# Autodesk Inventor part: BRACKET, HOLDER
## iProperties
Title: BRACKET, HOLDER
Author: J. DESIGNER
Revision Number: A
Created: 2000-11
Part Number: ex10-1
Project: ACME
User Status: ECO 20001
Description: HOLDER, BRACKET
Document SubType Name: Modeling
Designer: E. MOSS
Control State: 0
Master: False
Checked Out: False
PropertySet Name: Design Tracking Control
Shininess: 50.0
PropertySet Name: _Private Model Information
Density: 0.0
Volumn: 0.0
Area: 0.0
PropertySet Name: Model Information
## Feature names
1. Revolution1
2. Extrusion1
3. Extrusion2
4. Extrusion3
5. Extrusion4
6. Extrusion5
7. Extrusion6
8. Fillet1
9. Extrusion7
10. LARGE THRU HOLES [Hole]
11. Hole2
12. Hole3
13. Hole4
14. Extrusion8
15. Hole5
16. Hole6
17. Hole7
18. Hole8
19. Fillet2
20. Fillet3
21. Fillet4
22. Fillet5
23. Fillet6
